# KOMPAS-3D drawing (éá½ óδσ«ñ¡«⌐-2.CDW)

Referenced files: Вал выходной-2.CDW
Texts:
  Вал выходной
  Noncommercial version
  1. HB 260...280, кроме поверхности С.
  2. * - параметр, обеспечиваемый инструментом.
  3. Неуказанные радиусы r = 1,0 мм.
  Полировать
  Ra0.8
  Ra3.2
  Symbol type A
  max
  ТВЧ h=0,9...1,1 мм HRC 50...52
  Ra6.3
  Сталь 45 ГОСТ 1050-74
Dimensions and other numbers on the sheet: 70; 90; 16; 60; 58; 67; 2,5; 2 фаски; 9; 97; 136; 168; 188; 20; 42; 275; 353; 402; 55; 53; 0,012; 7; 0,4; 18; 1:1; 1; 0; 2; 3; 4; 5; 6; 8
